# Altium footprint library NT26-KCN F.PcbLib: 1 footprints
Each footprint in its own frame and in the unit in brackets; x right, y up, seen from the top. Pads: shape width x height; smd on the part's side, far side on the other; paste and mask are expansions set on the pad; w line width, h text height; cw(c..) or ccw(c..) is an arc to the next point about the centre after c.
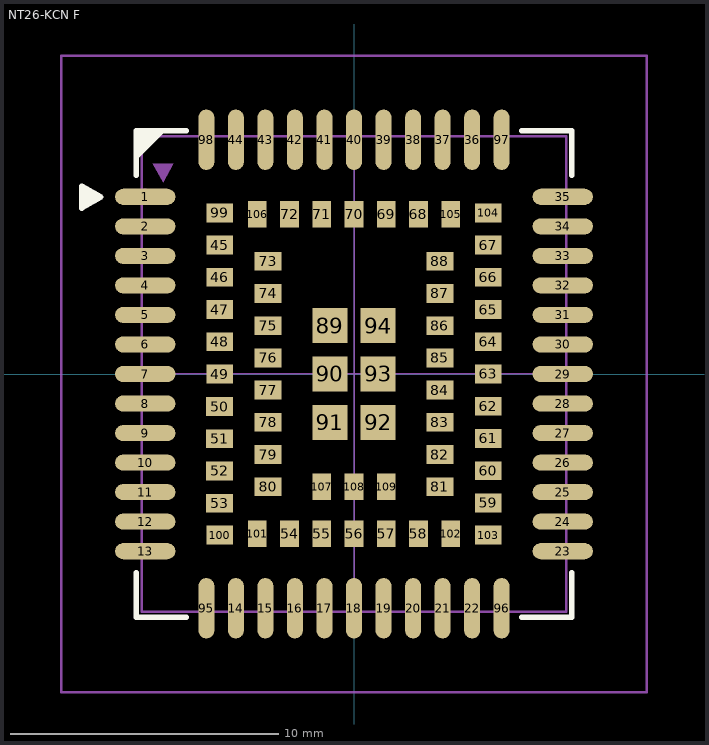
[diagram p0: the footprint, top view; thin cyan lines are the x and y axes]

## NT26-KCN F [mm]
height 2
pads (218):
  oval 2.25x0.6 smd mask+0.102: 1(-7.775,6.6) 2(-7.775,5.5) 3(-7.775,4.4) 4(-7.775,3.3) 5(-7.775,2.2) 6(-7.775,1.1) 7(-7.775,0) 8(-7.775,-1.1) 9(-7.775,-2.2) 10(-7.775,-3.3) 11(-7.775,-4.4) 12(-7.775,-5.5) 13(-7.775,-6.6) 23(7.775,-6.6) 24(7.775,-5.5) 25(7.775,-4.4) 26(7.775,-3.3) 27(7.775,-2.2) 28(7.775,-1.1) 29(7.775,0) 30(7.775,1.1) 31(7.775,2.2) 32(7.775,3.3) 33(7.775,4.4) 34(7.775,5.5) 35(7.775,6.6)
  oval 0.6x2.25 smd mask+0.102: 14(-4.4,-8.725) 15(-3.3,-8.725) 16(-2.2,-8.725) 17(-1.1,-8.725) 18(0,-8.725) 19(1.1,-8.725) 20(2.2,-8.725) 21(3.3,-8.725) 22(4.4,-8.725) 36(4.4,8.725) 37(3.3,8.725) 38(2.2,8.725) 39(1.1,8.725) 40(0,8.725) 41(-1.1,8.725) 42(-2.2,8.725) 43(-3.3,8.725) 44(-4.4,8.725) 95(-5.5,-8.725) 96(5.5,-8.725) 97(5.5,8.725) 98(-5.5,8.725)
  rect 1x0.7 smd: 45(-5,4.8) 46(-5,3.6) 47(-5,2.4) 48(-5,1.2) 49(-5,0) 50(-5.003,-1.211) 51(-5.003,-2.411) 52(-5.003,-3.611) 53(-5.003,-4.811) 59(5,-4.8) 60(5,-3.6) 61(5,-2.4) 62(5,-1.2) 63(5,0) 64(5,1.2) 65(5,2.4) 66(5,3.6) 67(5,4.8) 73(-3.2,4.2) 74(-3.2,3) 75(-3.2,1.8) 76(-3.2,0.6) 77(-3.2,-0.6) 78(-3.2,-1.8) 79(-3.2,-3) 80(-3.2,-4.2) 81(3.2,-4.2) 82(3.2,-3) 83(3.2,-1.8) 84(3.2,-0.6) 85(3.2,0.6) 86(3.2,1.8) 87(3.2,3) 88(3.2,4.2) 99(-5,6) 100(-5,-6) 103(5,-6) 104(5,6)
  rect 0.7x1 smd: 54(-2.4,-5.95) 55(-1.2,-5.95) 56(0,-5.95) 57(1.2,-5.95) 58(2.4,-5.95) 68(2.4,5.95) 69(1.2,5.95) 70(0,5.95) 71(-1.2,5.95) 72(-2.4,5.95) 101(-3.6,-5.95) 102(3.6,-5.95) 105(3.6,5.95) 106(-3.6,5.95) 107(-1.2,-4.2) 108(0,-4.2) 109(1.2,-4.2)
  rect 1.3x1.3 smd: 89(-0.9,1.8) 90(-0.9,0) 91(-0.9,-1.8) 92(0.9,-1.8) 93(0.9,0) 94(0.9,1.8)
  oval 1.5x0.6 on Mech1 mask+0.076: ""(-7.4,-6.6) ""(-7.4,-5.5) ""(-7.4,-4.4) ""(-7.4,-3.3) ""(-7.4,-2.2) ""(-7.4,-1.1) ""(-7.4,0) ""(-7.4,1.1) ""(-7.4,2.2) ""(-7.4,3.3) ""(-7.4,4.4) ""(-7.4,5.5) ""(-7.4,6.6) ""(7.4,-6.6) ""(7.4,-5.5) ""(7.4,-4.4) ""(7.4,-3.3) ""(7.4,-2.2) ""(7.4,-1.1) ""(7.4,0) ""(7.4,1.1) ""(7.4,2.2) ""(7.4,3.3) ""(7.4,4.4) ""(7.4,5.5) ""(7.4,6.6)
  oval 0.6x1.5 on Mech1 mask+0.076: ""(-5.5,-8.35) ""(-5.5,8.35) ""(-4.4,-8.35) ""(-4.4,8.35) ""(-3.3,-8.35) ""(-3.3,8.35) ""(-2.2,-8.35) ""(-2.2,8.35) ""(-1.1,-8.35) ""(-1.1,8.35) ""(0,-8.35) ""(0,8.35) ""(1.1,-8.35) ""(1.1,8.35) ""(2.2,-8.35) ""(2.2,8.35) ""(3.3,-8.35) ""(3.3,8.35) ""(4.4,-8.35) ""(4.4,8.35) ""(5.5,-8.35) ""(5.5,8.35)
  rect 1x0.7 on Mech1: ""(-5.003,-4.811) ""(-5.003,-0.011) ""(-5.003,-3.611) ""(-5.003,-2.411) ""(-5.003,-1.211) ""(-5,-6) ""(-5,1.2) ""(-5,2.4) ""(-5,3.6) ""(-5,4.8) ""(-5,6) ""(-3.2,-4.2) ""(-3.2,-3) ""(-3.2,-1.8) ""(-3.2,-0.6) ""(-3.2,0.6) ""(-3.2,1.8) ""(-3.2,3) ""(-3.2,4.2) ""(3.2,-4.2) ""(3.2,-3) ""(3.2,-1.8) ""(3.2,-0.6) ""(3.2,0.6) ""(3.2,1.8) ""(3.2,3) ""(3.2,4.2) ""(5,-6) ""(5,-4.8) ""(5,-3.6) ""(5,-2.4) ""(5,0) ""(5,1.2) ""(5,2.4) ""(5,3.6) ""(5,4.8) ""(5,6) ""(5,-1.2)
  rect 0.7x1 on Mech1: ""(-3.6,-5.95) ""(-3.6,5.95) ""(-2.4,-5.95) ""(-2.4,5.95) ""(-1.2,-5.95) ""(-1.2,5.95) ""(0,-5.95) ""(0,5.95) ""(1.2,5.95) ""(1.2,-5.95) ""(2.4,-5.95) ""(2.4,5.95) ""(3.6,-5.95) ""(3.6,5.95)
  rrect30% 0.7x1 on Mech1: ""(-1.2,-4.2) ""(0,-4.2) ""(1.2,-4.2)
  rect 1.3x1.3 on Mech1: ""(-0.9,-1.8) ""(-0.9,0) ""(-0.9,1.8) ""(0.9,-1.8) ""(0.9,0) ""(0.9,1.8)
Top Overlay:
  region: -10.144,6.175 -9.42,6.59 -10.144,7.002
  region: -8.108,9.057 -8.097,7.973 -7.023,9.047
  lines w0.199: -8.108,-7.406 -8.108,-9.057 -6.25,-9.057 ; -8.108,7.406 -8.108,9.057 -6.25,9.057 ; 6.25,-9.057 8.108,-9.057 8.108,-7.406 ; 6.25,9.057 8.108,9.057 8.108,7.406 ; -10.144,6.175 -10.144,7.002 -9.42,6.59 -10.144,6.175
Mechanical 1:
  region: -7.096,7.137 -7.495,7.837 -6.728,7.837
  lines w0.05: -7.9,0 0,0 ; 0,-8.85 0,0 ; 0,8.85 0,0 ; 7.9,0 0,0
  lines w0.1: 10.9,-11.85 10.9,11.85 ; 10.9,-11.85 10.9,11.85 ; 10.9,-11.85 -10.9,-11.85 -10.9,11.85 10.9,11.85 ; -7.9,-8.85 -7.9,8.85 7.9,8.85 7.9,-8.85 -7.9,-8.85
Mechanical 15:
  circle w0.35: c-7.775,6.6 r0.126
  lines w0.1: -7.9,-8.85 7.9,-8.85 7.9,8.85 -7.9,8.85 -7.9,-8.85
